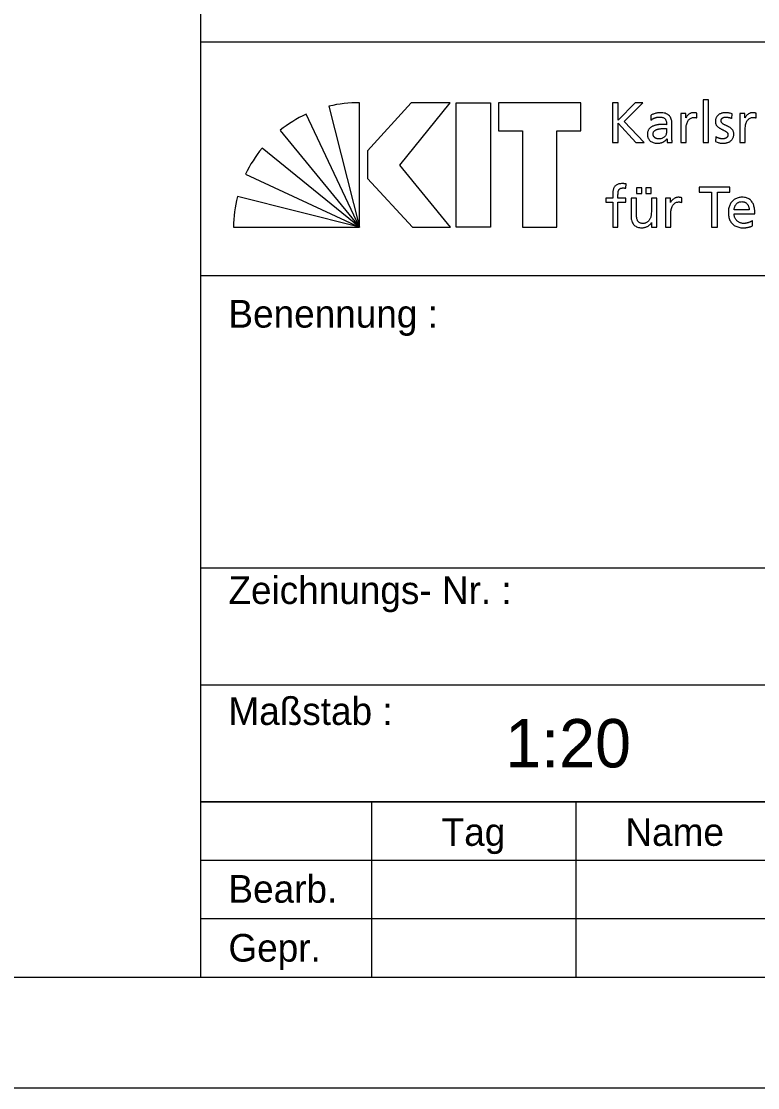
# Model space of a CAD drawing. Extents: x 0 to 8.4, y 0 to 5.94.
# Drawn here: x 6.3 to 7.367, y 0 to 1.543 of the extents above; entities that cross this region are included whole.
import ezdxf

# ---------------------------------------------------------------- set-up
doc = ezdxf.new("R2010")
doc.units = 0
doc.layers.add('90_Plankopf', color=7, linetype='Continuous')

msp = doc.modelspace()

# ---------------------------------------------------------------- linework, layer by layer
at = {"layer": '90_Plankopf'}
for p, q in [((6.56, 1.5136), (6.56, 1.7674)), ((6.56, 1.5136), (8.24, 1.5136)), ((6.7455, 1.4205), (6.7896, 1.2455)), ((6.7896, 1.2455), (6.7896, 1.4255)), ((7.1562, 1.4255), (7.1562, 1.3679)), ((6.7896, 1.2455), (6.7127, 1.4088)), ((7.2116, 1.407), (7.212, 1.4004)), ((7.2785, 1.4035), (7.2785, 1.4104)), ((7.3291, 1.4026), (7.3298, 1.4094)), ((7.3642, 1.4035), (7.3642, 1.4104)), ((7.2424, 1.3762), (7.2424, 1.3936)), ((6.6749, 1.3855), (6.7896, 1.2455)), ((7.2346, 1.388), (7.2346, 1.3843)), ((7.3059, 1.3762), (7.3055, 1.3692)), ((6.7896, 1.2455), (6.6487, 1.3595)), ((7.1562, 1.3679), (7.1644, 1.3679)), ((7.1901, 1.3679), (7.2022, 1.3679)), ((6.6248, 1.3221), (6.7896, 1.2455)), ((7.1755, 1.3017), (7.1758, 1.3079)), ((6.7896, 1.2455), (6.6132, 1.2896)), ((7.2565, 1.2811), (7.2565, 1.288)), ((7.3541, 1.2706), (7.3323, 1.2706)), ((7.3323, 1.2648), (7.3624, 1.2648)), ((7.3592, 1.2473), (7.3592, 1.255)), ((6.6073, 1.2455), (6.7896, 1.2455)), ((6.56, 1.1752), (8.24, 1.1752)), ((6.56, 0.7522), (8.24, 0.7522)), ((6.56, 0.583), (8.24, 0.583)), ((6.56, 0.4138), (8.24, 0.4138)), ((6.56, 0.4138), (8.24, 0.4138)), ((6.56, 0.4138), (8.24, 0.4138)), ((6.56, 0.4138), (8.24, 0.4138)), ((6.56, 0.16), (6.56, 0.4138)), ((6.8071, 0.4138), (6.8071, 0.16)), ((7.1035, 0.16), (7.1035, 0.4138)), ((6.56, 0.3292), (7.4, 0.3292)), ((6.56, 0.2446), (7.4, 0.2446)), ((6.56, 0.16), (8.24, 0.16)), ((6.56, 0.16), (8.24, 0.16))]:
    msp.add_line(p, q, dxfattribs=at)
for points in [[(0, 0), (8.4, 0), (8.4, 5.94), (0, 5.94)], [(0.16, 0.16), (8.24, 0.16), (8.24, 5.78), (0.16, 5.78)], [(6.9213, 1.4255), (6.8647, 1.4255), (6.8015, 1.3558), (6.8015, 1.3156), (6.8668, 1.2455), (6.9217, 1.2455), (6.8484, 1.3351)], [(6.9794, 1.4255), (6.9794, 1.2455), (6.93, 1.2455), (6.93, 1.4255)], [(6.9912, 1.4255), (6.9912, 1.385), (7.026, 1.385), (7.026, 1.2455), (7.0754, 1.2455), (7.0754, 1.385), (7.1102, 1.385), (7.1102, 1.4255)]]:
    msp.add_lwpolyline(points, close=True, dxfattribs=at)
for points in [[(6.56, 0.4138), (6.56, 1.5136)], [(7.2022, 1.3679), (7.1729, 1.3983), (7.2, 1.4255), (7.189, 1.4255), (7.1644, 1.4002), (7.1644, 1.4255), (7.1562, 1.4255)], [(7.2876, 1.3679), (7.2954, 1.3679), (7.2954, 1.4298), (7.2876, 1.4298), (7.2876, 1.3679)], [(7.2624, 1.4035), (7.2623, 1.4035), (7.2623, 1.41), (7.255, 1.41), (7.255, 1.3679), (7.2628, 1.3679), (7.2628, 1.3871)], [(7.3481, 1.4035), (7.348, 1.4035), (7.348, 1.41), (7.3407, 1.41), (7.3407, 1.3679), (7.3485, 1.3679), (7.3485, 1.3871)], [(7.1644, 1.3679), (7.1644, 1.3961), (7.1901, 1.3679)], [(7.2353, 1.3734), (7.2354, 1.3734), (7.2354, 1.3679), (7.2427, 1.3679)], [(7.1911, 1.3023), (7.1911, 1.2941), (7.1988, 1.2941), (7.1988, 1.3023), (7.1911, 1.3023)], [(7.2046, 1.3023), (7.2046, 1.2941), (7.2124, 1.2941), (7.2124, 1.3023), (7.2046, 1.3023)], [(7.2998, 1.2455), (7.3081, 1.2455), (7.3081, 1.2959), (7.326, 1.2959), (7.326, 1.3031), (7.2819, 1.3031), (7.2819, 1.2959), (7.2998, 1.2959), (7.2998, 1.2455)], [(7.1565, 1.2915), (7.1565, 1.2876), (7.1466, 1.2876), (7.1466, 1.2814), (7.1565, 1.2814), (7.1565, 1.2455), (7.1642, 1.2455), (7.1642, 1.2814), (7.1754, 1.2814), (7.1754, 1.2876), (7.1642, 1.2876), (7.1642, 1.2922)], [(7.1908, 1.2658), (7.1908, 1.2876), (7.1831, 1.2876), (7.1831, 1.2626)], [(7.2203, 1.2455), (7.2203, 1.2876), (7.2125, 1.2876), (7.2125, 1.2681)], [(7.2404, 1.2811), (7.2403, 1.2811), (7.2403, 1.2876), (7.233, 1.2876), (7.233, 1.2455), (7.2408, 1.2455), (7.2408, 1.2647)], [(7.2126, 1.2522), (7.2128, 1.2522), (7.2128, 1.2455), (7.2203, 1.2455)], [(8.24, 0.4138), (6.56, 0.4138)], [(6.56, 0.4138), (6.56, 0.4138)], [(6.56, 0.16), (8.24, 0.16)]]:
    msp.add_lwpolyline(points, dxfattribs=at)
for centre, start, end in [((6.789, 1.2349), 89.8053, 103.1895), ((6.7932, 1.2362), 115.0126, 128.3968), ((6.7963, 1.2391), 140.7898, 154.174), ((6.7978, 1.2426), 165.7222, 179.1064)]:
    msp.add_arc(centre, 0.1906, start, end, dxfattribs=at)
for points in [[(7.2424, 1.3936), (7.2424, 1.3974), (7.2418, 1.4006), (7.2407, 1.4032), (7.2395, 1.4058), (7.2377, 1.4077), (7.2352, 1.409), (7.2327, 1.4103), (7.2294, 1.411), (7.2254, 1.411), (7.2228, 1.411), (7.2203, 1.4106), (7.218, 1.4099), (7.2156, 1.4092), (7.2135, 1.4082), (7.2116, 1.407)], [(7.212, 1.4004), (7.2131, 1.4013), (7.2143, 1.4021), (7.2156, 1.4027), (7.2169, 1.4034), (7.2183, 1.4039), (7.2198, 1.4042), (7.2213, 1.4046), (7.2227, 1.4047), (7.2242, 1.4047), (7.2268, 1.4047), (7.2288, 1.4043), (7.2304, 1.4035), (7.2319, 1.4027), (7.233, 1.4015), (7.2336, 1.3998), (7.2343, 1.3982), (7.2346, 1.3962), (7.2346, 1.3937)], [(7.2785, 1.4104), (7.278, 1.4105), (7.2775, 1.4106), (7.277, 1.4107), (7.2765, 1.4108), (7.276, 1.4109), (7.2754, 1.4109), (7.2748, 1.411), (7.2742, 1.411), (7.2734, 1.411), (7.2719, 1.411), (7.2705, 1.4107), (7.269, 1.41), (7.2676, 1.4094), (7.2664, 1.4085), (7.2652, 1.4074), (7.2641, 1.4063), (7.2631, 1.405), (7.2624, 1.4035)], [(7.3298, 1.4094), (7.3283, 1.4098), (7.3267, 1.4102), (7.3252, 1.4105), (7.3236, 1.4108), (7.3219, 1.411), (7.3201, 1.411), (7.3181, 1.411), (7.3161, 1.4107), (7.3143, 1.4102), (7.3125, 1.4097), (7.3109, 1.4089), (7.3096, 1.4078), (7.3082, 1.4067), (7.3072, 1.4054), (7.3064, 1.4038), (7.3057, 1.4021), (7.3053, 1.4002), (7.3053, 1.398), (7.3053, 1.3964), (7.3056, 1.3949), (7.3063, 1.3937), (7.3069, 1.3925), (7.3078, 1.3914), (7.3089, 1.3905), (7.31, 1.3896), (7.3112, 1.3888), (7.3125, 1.3881), (7.3138, 1.3874), (7.3151, 1.3867), (7.3163, 1.3861), (7.3176, 1.3855), (7.3188, 1.3849), (7.3199, 1.3842), (7.321, 1.3836), (7.3219, 1.3829), (7.3225, 1.3821), (7.3232, 1.3813), (7.3235, 1.3803), (7.3235, 1.3792), (7.3235, 1.3781), (7.3233, 1.3771), (7.3228, 1.3764), (7.3223, 1.3756), (7.3217, 1.375), (7.3209, 1.3745), (7.3201, 1.374), (7.3193, 1.3737), (7.3183, 1.3735), (7.3174, 1.3733), (7.3165, 1.3732), (7.3156, 1.3732), (7.3148, 1.3732), (7.3139, 1.3733), (7.3128, 1.3735), (7.3117, 1.3737), (7.3105, 1.3741), (7.3093, 1.3745), (7.3081, 1.375), (7.307, 1.3755), (7.3059, 1.3762)], [(7.3055, 1.3692), (7.3073, 1.3683), (7.3092, 1.3677), (7.3112, 1.3674), (7.3131, 1.367), (7.3151, 1.3669), (7.3171, 1.3669), (7.319, 1.3669), (7.3208, 1.3672), (7.3225, 1.3677), (7.3243, 1.3682), (7.3259, 1.369), (7.3273, 1.3701), (7.3286, 1.3712), (7.3297, 1.3726), (7.3305, 1.3742), (7.3314, 1.3759), (7.3318, 1.3778), (7.3318, 1.38), (7.3318, 1.382), (7.3314, 1.3836), (7.3308, 1.3849), (7.3301, 1.3862), (7.3292, 1.3874), (7.3282, 1.3883), (7.3271, 1.3892), (7.3259, 1.39), (7.3246, 1.3907), (7.3233, 1.3914), (7.322, 1.392), (7.3207, 1.3925), (7.3194, 1.3931), (7.3182, 1.3937), (7.3172, 1.3943), (7.3161, 1.395), (7.3152, 1.3957), (7.3145, 1.3965), (7.3139, 1.3974), (7.3136, 1.3984), (7.3135, 1.3996), (7.3136, 1.4008), (7.3139, 1.4017), (7.3146, 1.4025), (7.3153, 1.4032), (7.3162, 1.4038), (7.3173, 1.4042), (7.3184, 1.4046), (7.3196, 1.4047), (7.321, 1.4047), (7.3214, 1.4047), (7.322, 1.4047), (7.3228, 1.4046), (7.3235, 1.4044), (7.3243, 1.4043), (7.3251, 1.4041), (7.3259, 1.4039), (7.3267, 1.4036), (7.3274, 1.4034), (7.3281, 1.4031), (7.3287, 1.4029), (7.3291, 1.4026)], [(7.3642, 1.4104), (7.3637, 1.4105), (7.3632, 1.4106), (7.3627, 1.4107), (7.3622, 1.4108), (7.3617, 1.4109), (7.3611, 1.4109), (7.3605, 1.411), (7.3599, 1.411), (7.3591, 1.411), (7.3576, 1.411), (7.3562, 1.4107), (7.3547, 1.41), (7.3533, 1.4094), (7.3521, 1.4085), (7.3509, 1.4074), (7.3498, 1.4063), (7.3488, 1.405), (7.3481, 1.4035)], [(7.2346, 1.3937), (7.2336, 1.3938), (7.2327, 1.3938), (7.2318, 1.3939), (7.2309, 1.3939), (7.23, 1.3939), (7.2292, 1.3939), (7.2283, 1.3939), (7.2274, 1.3939), (7.2264, 1.3939), (7.2247, 1.3939), (7.223, 1.3938), (7.2213, 1.3935), (7.2195, 1.3932), (7.2177, 1.3927), (7.216, 1.3921), (7.2143, 1.3914), (7.2128, 1.3906), (7.2114, 1.3895), (7.21, 1.3884), (7.2089, 1.3871), (7.2081, 1.3856), (7.2072, 1.384), (7.2068, 1.3822), (7.2068, 1.38), (7.2068, 1.377), (7.2075, 1.3745), (7.2088, 1.3726), (7.2101, 1.3706), (7.2119, 1.3692), (7.2142, 1.3683), (7.2165, 1.3674), (7.2192, 1.3669), (7.2222, 1.3669), (7.224, 1.3669), (7.2256, 1.3672), (7.227, 1.3676), (7.2284, 1.368), (7.2297, 1.3685), (7.2307, 1.3692), (7.2318, 1.3698), (7.2327, 1.3705), (7.2335, 1.3713), (7.2342, 1.372), (7.2348, 1.3727), (7.2353, 1.3734)], [(7.2628, 1.3871), (7.2628, 1.3906), (7.2633, 1.3937), (7.2642, 1.3962), (7.2651, 1.3988), (7.2665, 1.4008), (7.2682, 1.4021), (7.2699, 1.4035), (7.2719, 1.4042), (7.2742, 1.4042), (7.2749, 1.4042), (7.2756, 1.4042), (7.2764, 1.4041), (7.2771, 1.404), (7.2778, 1.4038), (7.2785, 1.4035)], [(7.3485, 1.3871), (7.3485, 1.3906), (7.349, 1.3937), (7.3499, 1.3962), (7.3508, 1.3988), (7.3522, 1.4008), (7.3539, 1.4021), (7.3556, 1.4035), (7.3576, 1.4042), (7.3599, 1.4042), (7.3606, 1.4042), (7.3613, 1.4042), (7.3621, 1.4041), (7.3628, 1.404), (7.3635, 1.4038), (7.3642, 1.4035)], [(7.2346, 1.3843), (7.2346, 1.3822), (7.2342, 1.3803), (7.2333, 1.3786), (7.2324, 1.3769), (7.2311, 1.3756), (7.2293, 1.3747), (7.2276, 1.3737), (7.2254, 1.3732), (7.2229, 1.3732), (7.222, 1.3732), (7.2211, 1.3734), (7.2202, 1.3736), (7.2193, 1.3739), (7.2184, 1.3744), (7.2176, 1.3749), (7.2169, 1.3755), (7.2162, 1.3763), (7.2158, 1.3771), (7.2153, 1.3779), (7.2151, 1.3789), (7.215, 1.38), (7.2151, 1.3815), (7.2154, 1.3828), (7.2162, 1.3837), (7.2169, 1.3847), (7.2178, 1.3855), (7.219, 1.3861), (7.2201, 1.3867), (7.2214, 1.3871), (7.2227, 1.3874), (7.224, 1.3877), (7.2253, 1.3879), (7.2265, 1.388), (7.2277, 1.3881), (7.2288, 1.3881), (7.2297, 1.3881), (7.2305, 1.3881), (7.2313, 1.3881), (7.2321, 1.3881), (7.233, 1.388), (7.2338, 1.388), (7.2346, 1.388)], [(7.2427, 1.3679), (7.2426, 1.3683), (7.2426, 1.3689), (7.2425, 1.3695), (7.2425, 1.3702), (7.2424, 1.3711), (7.2424, 1.3722), (7.2424, 1.3733), (7.2424, 1.3746), (7.2424, 1.3762)], [(7.1758, 1.3079), (7.175, 1.308), (7.1742, 1.3082), (7.1734, 1.3083), (7.1725, 1.3084), (7.1716, 1.3084), (7.1706, 1.3084), (7.1678, 1.3084), (7.1654, 1.308), (7.1636, 1.3072), (7.1617, 1.3064), (7.1603, 1.3053), (7.1592, 1.3038), (7.1582, 1.3023), (7.1575, 1.3005), (7.1571, 1.2985), (7.1567, 1.2964), (7.1565, 1.2941), (7.1565, 1.2915)], [(7.1642, 1.2922), (7.1642, 1.2936), (7.1643, 1.2949), (7.1645, 1.2961), (7.1646, 1.2973), (7.165, 1.2984), (7.1655, 1.2993), (7.166, 1.3002), (7.1668, 1.3009), (7.1678, 1.3014), (7.1688, 1.3019), (7.1701, 1.3021), (7.1718, 1.3021), (7.1724, 1.3021), (7.1731, 1.3021), (7.1738, 1.302), (7.1744, 1.3019), (7.175, 1.3018), (7.1755, 1.3017)], [(7.2565, 1.288), (7.256, 1.2881), (7.2555, 1.2882), (7.255, 1.2883), (7.2545, 1.2884), (7.254, 1.2885), (7.2534, 1.2885), (7.2528, 1.2886), (7.2522, 1.2886), (7.2514, 1.2886), (7.2499, 1.2886), (7.2485, 1.2883), (7.247, 1.2876), (7.2456, 1.287), (7.2444, 1.2861), (7.2432, 1.285), (7.2421, 1.2839), (7.2411, 1.2826), (7.2404, 1.2811)], [(7.2408, 1.2647), (7.2408, 1.2682), (7.2413, 1.2713), (7.2422, 1.2738), (7.2432, 1.2764), (7.2445, 1.2784), (7.2462, 1.2797), (7.2479, 1.2811), (7.2499, 1.2818), (7.2522, 1.2818), (7.2529, 1.2819), (7.2536, 1.2818), (7.2544, 1.2817), (7.2551, 1.2816), (7.2558, 1.2814), (7.2565, 1.2811)], [(7.3624, 1.2648), (7.3624, 1.2682), (7.3621, 1.2714), (7.3614, 1.2743), (7.3608, 1.2772), (7.3598, 1.2797), (7.3584, 1.2818), (7.3569, 1.2839), (7.355, 1.2856), (7.3526, 1.2868), (7.3502, 1.288), (7.3473, 1.2886), (7.3438, 1.2886), (7.3408, 1.2886), (7.3381, 1.2881), (7.3357, 1.287), (7.3333, 1.286), (7.3312, 1.2845), (7.3295, 1.2826), (7.3277, 1.2807), (7.3264, 1.2785), (7.3255, 1.2759), (7.3246, 1.2733), (7.3241, 1.2705), (7.3241, 1.2673), (7.3241, 1.2639), (7.3245, 1.2608), (7.3254, 1.258), (7.3262, 1.2552), (7.3276, 1.2528), (7.3294, 1.2508), (7.3312, 1.2488), (7.3334, 1.2472), (7.3362, 1.2462), (7.3389, 1.2451), (7.3421, 1.2446), (7.3459, 1.2445), (7.3482, 1.2446), (7.3501, 1.2447), (7.3517, 1.245), (7.3533, 1.2453), (7.3547, 1.2457), (7.3559, 1.2461), (7.3571, 1.2465), (7.3582, 1.2469), (7.3592, 1.2473)], [(7.3323, 1.2706), (7.3325, 1.272), (7.3328, 1.2734), (7.3333, 1.2747), (7.3338, 1.2761), (7.3344, 1.2774), (7.3354, 1.2785), (7.3362, 1.2797), (7.3374, 1.2806), (7.3387, 1.2813), (7.3401, 1.282), (7.3417, 1.2823), (7.3436, 1.2823), (7.3453, 1.2823), (7.3468, 1.282), (7.3481, 1.2814), (7.3494, 1.2808), (7.3505, 1.28), (7.3514, 1.2789), (7.3523, 1.2778), (7.353, 1.2766), (7.3534, 1.2752), (7.3539, 1.2738), (7.3541, 1.2722), (7.3541, 1.2706)], [(7.2125, 1.2681), (7.2125, 1.2656), (7.2123, 1.2632), (7.2118, 1.2611), (7.2113, 1.259), (7.2105, 1.2572), (7.2095, 1.2556), (7.2084, 1.2541), (7.2071, 1.2529), (7.2055, 1.2521), (7.2039, 1.2512), (7.2019, 1.2508), (7.1997, 1.2508), (7.1975, 1.2509), (7.1957, 1.2516), (7.1944, 1.2527), (7.1931, 1.2538), (7.1922, 1.2555), (7.1916, 1.2577), (7.1911, 1.2598), (7.1908, 1.2626), (7.1908, 1.2658)], [(7.1831, 1.2626), (7.1831, 1.2588), (7.1836, 1.2556), (7.1847, 1.2529), (7.1859, 1.2502), (7.1876, 1.2481), (7.1899, 1.2467), (7.1922, 1.2453), (7.1952, 1.2446), (7.1988, 1.2445), (7.2008, 1.2446), (7.2027, 1.2449), (7.2045, 1.2455), (7.2063, 1.2461), (7.2079, 1.247), (7.2093, 1.2481), (7.2107, 1.2492), (7.2118, 1.2506), (7.2126, 1.2522)], [(7.3592, 1.255), (7.3587, 1.2546), (7.358, 1.2542), (7.357, 1.2537), (7.3561, 1.2532), (7.3551, 1.2528), (7.3539, 1.2523), (7.3527, 1.2519), (7.3514, 1.2515), (7.3501, 1.2512), (7.3488, 1.251), (7.3475, 1.2508), (7.3462, 1.2508), (7.3443, 1.2508), (7.3426, 1.2512), (7.3409, 1.2518), (7.3393, 1.2525), (7.3378, 1.2535), (7.3365, 1.2547), (7.3352, 1.2559), (7.3342, 1.2574), (7.3335, 1.2591), (7.3327, 1.2609), (7.3323, 1.2628), (7.3323, 1.2648)]]:
    msp.add_open_spline(points, degree=3, dxfattribs=at)

# ---------------------------------------------------------------- texts
for s, height, p in [('Benennung :', 0.04, (6.6, 1.1)), ('Zeichnungs- Nr. :', 0.04, (6.6, 0.7)), ('Maßstab :', 0.04, (6.6, 0.525)), ('1:20    ', 0.07, (7.0009, 0.4635)), ('Tag', 0.04, (6.9088, 0.35)), ('Name', 0.04, (7.175, 0.35)), ('Bearb.', 0.04, (6.6, 0.2677)), ('Gepr.', 0.04, (6.6, 0.1824))]:
    msp.add_text(s, height=height, dxfattribs=at).set_placement(p)

doc.saveas('drawing.dxf')
